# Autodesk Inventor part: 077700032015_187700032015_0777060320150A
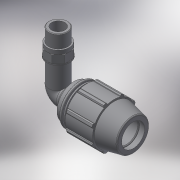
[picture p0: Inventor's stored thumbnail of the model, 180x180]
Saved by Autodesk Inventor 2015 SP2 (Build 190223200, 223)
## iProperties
Created: 2017-02
Part Number: 077700032015_187700032015_0777060320150A
Material: Generic
Description: PLASSON 90° ELBOW MALE WITH INTEGRAL BRASS THREAD 32-1.1/2"
Document SubType Name: Modeling
Designer: KIM
Mass: 174.249 g
Surface Area: 431.906 cm^2
Volume: 174.249 cm^3
Density: 1 g/cm^3
Appearance: Default
Author: KIM
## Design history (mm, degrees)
derived "07770.ipt"
feature "Solid1::07770.ipt"
tag "TaggingFeature1"
body "Solid1"
other parameters: "d2" = 32, "d4" = 8.66667, "d5" = 26, "d7" = 64, "d9" = 14.85714, "d11" = 3.46667, "d13" = 120 deg, "d14" = 44.8, "d15" = 12 deg, "d16" = 55.68, "d18" = 1.6, "d19" = 35 deg, "d20" = 17.5 deg, "d21" = 59.52, "d23" = 0, "d25" = 360 deg, "d27" = 1.28, "d33" = 0.64, "d42" = 38.48, "d43" = 1.92, "d46" = 0.96, "d51" = 104, "d68" = 6.93333, "d72" = 82, "d73" = 47.803, "d74" = 22, "d75" = 54.97345, "d76" = 33.4621, "d79" = 19.1212, "d80" = 1.43409, "d83" = 0, "d84" = 0, "d91" = 48, "d93" = 67, "d94" = 47.803, "d95" = 33.4621, "d96" = 6.93333, "d97" = 50 deg, "d98" = 1.73333, "d99" = 54.0096, "d100" = 1.73333, "d101" = 1.73333, "d105" = 2.2, "d106" = 57.3636, "d107" = 22, "d108" = 13.2, "d109" = 0, "d_" = 32, "E_" = 64, "A_" = 104, "l_" = 67, "l_2" = 22, "A_1" = 82, "R_" = 47.803
